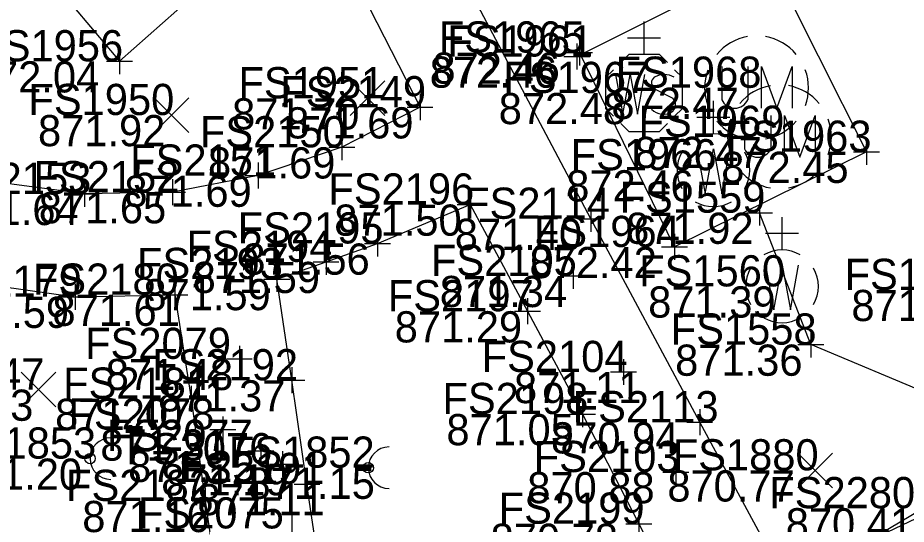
# Model space of a CAD drawing. Extents: x 1479420 to 1479833, y 379731 to 380103.
# Drawn here: x 1479654.58 to 1479688.81, y 379957.51 to 379977.01 of the extents above; entities that cross this region are included whole.
import ezdxf

# ---------------------------------------------------------------- set-up
doc = ezdxf.new("R2010")
doc.units = 0
for name, color, linetype in [('PV_X_Walk', 7, 'Continuous'), ('RD_X_Concrete_Pad', 7, 'Continuous'), ('SV_X_Random_Point', 7, 'Continuous'), ('SV_X_Shot_Marker', 7, 'Continuous'), ('SV_X_Text_Elevation', 7, 'Continuous'), ('SV_X_Text_Name', 7, 'Continuous'), ('UT_X_Gas', 7, 'Continuous'), ('UT_X_Misc_Cells', 7, 'Continuous'), ('UT_X_Unknown_Cells', 7, 'Continuous'), ('UT_X_Water', 7, 'Continuous'), ('UT_X_Water_Cells', 7, 'Continuous')]:
    doc.layers.add(name, color=color, linetype=linetype)

msp = doc.modelspace()

# ---------------------------------------------------------------- linework, layer by layer
at = {"layer": 'PV_X_Walk'}
for points in [[(1479508.898, 380098.739), (1479528.424, 380079.592), (1479545.906, 380063.234), (1479563.416, 380046.674), (1479583.683, 380027.557), (1479601.433, 380010.982), (1479618.885, 379994.721), (1479633.506, 379980.864), (1479639.156, 379975.367), (1479642.136, 379972.51), (1479646.219, 379969.763), (1479649.18, 379968.041), (1479652.865, 379966.819), (1479656.787, 379966.268), (1479660.633, 379966.347), (1479661.26, 379962.343), (1479661.797, 379958.407), (1479662.398, 379954.371), (1479663.052, 379950.601), (1479663.586, 379946.455), (1479663.663, 379946.474), (1479664.156, 379942.194)], [(1479666.468, 379980.646), (1479670.079, 379973.563), (1479667.067, 379972.021), (1479663.844, 379970.931), (1479660.54, 379970.294), (1479657.156, 379970.227), (1479653.854, 379970.663), (1479650.604, 379971.558), (1479648.889, 379972.524), (1479644.738, 379975.562), (1479637.768, 379982.016)], [(1479697.028, 379961.469), (1479684.159, 379955.33), (1479680.855, 379961.435), (1479676.661, 379969.27), (1479670.256, 379981.373)], [(1479667.32, 379947.167), (1479666.943, 379951.265), (1479666.294, 379955.174), (1479665.724, 379959.058), (1479665.135, 379963.052), (1479664.561, 379966.951), (1479666.457, 379967.611), (1479668.439, 379968.319), (1479672.009, 379969.818), (1479674.225, 379965.709), (1479676.339, 379961.752), (1479678.506, 379957.53), (1479680.531, 379953.578)]]:
    msp.add_lwpolyline(points, dxfattribs=at)
at = {"layer": 'RD_X_Concrete_Pad'}
for points in [[(1479657.099, 379986.097), (1479652.76, 379982.133), (1479658.499, 379975.334), (1479662.918, 379979.259), (1479657.078, 379986.008)], [(1479676.121, 379975.516), (1479683.555, 379979.257), (1479687.279, 379971.85), (1479679.881, 379968.184), (1479676.227, 379975.671)]]:
    msp.add_lwpolyline(points, dxfattribs=at)
at = {"layer": 'SV_X_Random_Point'}
for p, q in [((1479667.386, 379973.243), (1479668.72, 379974.578)), ((1479667.386, 379974.578), (1479668.72, 379973.243)), ((1479659.831, 379972.598), (1479661.165, 379973.933)), ((1479659.831, 379973.933), (1479661.165, 379972.598)), ((1479654.716, 379962.025), (1479656.05, 379963.36)), ((1479654.716, 379963.36), (1479656.05, 379962.025)), ((1479684.64, 379958.916), (1479685.974, 379960.251)), ((1479684.64, 379960.251), (1479685.974, 379958.916))]:
    msp.add_line(p, q, dxfattribs=at)
at = {"layer": 'SV_X_Shot_Marker'}
for p, q in [((1479676.121, 379976.016), (1479676.121, 379975.016)), ((1479676.227, 379976.171), (1479676.227, 379975.171)), ((1479658.499, 379975.834), (1479658.499, 379974.834)), ((1479675.727, 379975.671), (1479676.727, 379975.671)), ((1479676.227, 379975.671), (1479676.227, 379975.671)), ((1479657.999, 379975.334), (1479658.999, 379975.334)), ((1479658.499, 379975.334), (1479658.499, 379975.334)), ((1479675.621, 379975.516), (1479676.621, 379975.516)), ((1479676.121, 379975.516), (1479676.121, 379975.516)), ((1479670.079, 379974.063), (1479670.079, 379973.063)), ((1479669.579, 379973.563), (1479670.579, 379973.563)), ((1479670.079, 379973.563), (1479670.079, 379973.563)), ((1479667.067, 379972.521), (1479667.067, 379971.521)), ((1479687.279, 379972.35), (1479687.279, 379971.35)), ((1479666.567, 379972.021), (1479667.567, 379972.021)), ((1479667.067, 379972.021), (1479667.067, 379972.021)), ((1479686.779, 379971.85), (1479687.779, 379971.85)), ((1479687.279, 379971.85), (1479687.279, 379971.85)), ((1479663.844, 379971.431), (1479663.844, 379970.431)), ((1479660.54, 379970.794), (1479660.54, 379969.794)), ((1479663.344, 379970.931), (1479664.344, 379970.931)), ((1479663.844, 379970.931), (1479663.844, 379970.931)), ((1479657.156, 379970.727), (1479657.156, 379969.727)), ((1479656.656, 379970.227), (1479657.656, 379970.227)), ((1479657.156, 379970.227), (1479657.156, 379970.227)), ((1479660.04, 379970.294), (1479661.04, 379970.294)), ((1479660.54, 379970.294), (1479660.54, 379970.294)), ((1479672.009, 379970.318), (1479672.009, 379969.318)), ((1479671.509, 379969.818), (1479672.509, 379969.818)), ((1479672.009, 379969.818), (1479672.009, 379969.818)), ((1479676.661, 379969.77), (1479676.661, 379968.77)), ((1479683.162, 379970.005), (1479683.162, 379969.005)), ((1479682.662, 379969.505), (1479683.662, 379969.505)), ((1479683.162, 379969.505), (1479683.162, 379969.505)), ((1479676.161, 379969.27), (1479677.161, 379969.27)), ((1479676.661, 379969.27), (1479676.661, 379969.27)), ((1479668.439, 379968.819), (1479668.439, 379967.819)), ((1479679.881, 379968.684), (1479679.881, 379967.684)), ((1479666.457, 379968.111), (1479666.457, 379967.111)), ((1479667.939, 379968.319), (1479668.939, 379968.319)), ((1479668.439, 379968.319), (1479668.439, 379968.319)), ((1479679.381, 379968.184), (1479680.381, 379968.184)), ((1479679.881, 379968.184), (1479679.881, 379968.184)), ((1479664.561, 379967.451), (1479664.561, 379966.451)), ((1479665.957, 379967.611), (1479666.957, 379967.611)), ((1479666.457, 379967.611), (1479666.457, 379967.611)), ((1479675.979, 379967.57), (1479675.979, 379966.57)), ((1479675.479, 379967.07), (1479676.479, 379967.07)), ((1479675.979, 379967.07), (1479675.979, 379967.07)), ((1479656.787, 379966.768), (1479656.787, 379965.768)), ((1479660.633, 379966.847), (1479660.633, 379965.847)), ((1479664.061, 379966.951), (1479665.061, 379966.951)), ((1479664.561, 379966.951), (1479664.561, 379966.951)), ((1479660.133, 379966.347), (1479661.133, 379966.347)), ((1479660.633, 379966.347), (1479660.633, 379966.347)), ((1479656.287, 379966.268), (1479657.287, 379966.268)), ((1479656.787, 379966.268), (1479656.787, 379966.268)), ((1479674.225, 379966.209), (1479674.225, 379965.209)), ((1479673.725, 379965.709), (1479674.725, 379965.709)), ((1479674.225, 379965.709), (1479674.225, 379965.709)), ((1479685.134, 379964.926), (1479685.134, 379963.926)), ((1479663.118, 379964.375), (1479663.118, 379963.375)), ((1479684.634, 379964.426), (1479685.634, 379964.426)), ((1479685.134, 379964.426), (1479685.134, 379964.426)), ((1479662.618, 379963.875), (1479663.618, 379963.875)), ((1479663.118, 379963.875), (1479663.118, 379963.875)), ((1479677.924, 379963.871), (1479677.924, 379962.871)), ((1479665.135, 379963.552), (1479665.135, 379962.552)), ((1479677.424, 379963.371), (1479678.424, 379963.371)), ((1479677.924, 379963.371), (1479677.924, 379963.371)), ((1479664.635, 379963.052), (1479665.635, 379963.052)), ((1479665.135, 379963.052), (1479665.135, 379963.052)), ((1479661.26, 379962.843), (1479661.26, 379961.843)), ((1479660.76, 379962.343), (1479661.76, 379962.343)), ((1479661.26, 379962.343), (1479661.26, 379962.343)), ((1479676.339, 379962.252), (1479676.339, 379961.252)), ((1479680.855, 379961.935), (1479680.855, 379960.935)), ((1479662.476, 379961.658), (1479662.476, 379960.658)), ((1479675.839, 379961.752), (1479676.839, 379961.752)), ((1479676.339, 379961.752), (1479676.339, 379961.752)), ((1479680.355, 379961.435), (1479681.355, 379961.435)), ((1479680.855, 379961.435), (1479680.855, 379961.435)), ((1479661.976, 379961.158), (1479662.976, 379961.158)), ((1479662.476, 379961.158), (1479662.476, 379961.158)), ((1479663.944, 379960.834), (1479663.944, 379959.834)), ((1479663.444, 379960.334), (1479664.444, 379960.334)), ((1479663.944, 379960.334), (1479663.944, 379960.334)), ((1479664.775, 379960.32), (1479664.775, 379959.32)), ((1479679.938, 379960.018), (1479679.938, 379959.018)), ((1479664.275, 379959.82), (1479665.275, 379959.82)), ((1479664.775, 379959.82), (1479664.775, 379959.82)), ((1479665.724, 379959.558), (1479665.724, 379958.558)), ((1479679.438, 379959.518), (1479680.438, 379959.518)), ((1479679.938, 379959.518), (1479679.938, 379959.518)), ((1479661.797, 379958.907), (1479661.797, 379957.907)), ((1479665.224, 379959.058), (1479666.224, 379959.058)), ((1479665.724, 379959.058), (1479665.724, 379959.058)), ((1479661.297, 379958.407), (1479662.297, 379958.407)), ((1479661.797, 379958.407), (1479661.797, 379958.407)), ((1479665.144, 379957.847), (1479665.144, 379956.847)), ((1479678.506, 379958.03), (1479678.506, 379957.03)), ((1479678.006, 379957.53), (1479679.006, 379957.53)), ((1479678.506, 379957.53), (1479678.506, 379957.53))]:
    msp.add_line(p, q, dxfattribs=at)
at = {"layer": 'UT_X_Gas'}
msp.add_lwpolyline([(1479590.076, 380006.869), (1479598.835, 379999.983), (1479606.591, 379993.985), (1479615.604, 379985.249), (1479623.747, 379977.629), (1479632.184, 379969.538), (1479638.836, 379962.809), (1479646.785, 379955.438), (1479652.981, 379949.433), (1479657.465, 379945.964), (1479660.591, 379945.024), (1479670.935, 379949.08), (1479679.157, 379953.065), (1479685.442, 379955.742), (1479689.462, 379958.127), (1479696.956, 379963.013), (1479705.088, 379967.488), (1479713.465, 379971.226), (1479723.024, 379975.676), (1479732.065, 379980.116), (1479742.535, 379985.018)], dxfattribs=at)
at = {"layer": 'UT_X_Misc_Cells'}
for centre in [(1479657.365, 379960.036), (1479668.087, 379959.686)]:
    msp.add_circle(centre, 0.2, dxfattribs=at)
for centre in [(1479658.165, 379960.036), (1479668.887, 379959.686)]:
    msp.add_arc(centre, 0.8, 90, 270, dxfattribs=at)
at = {"layer": 'UT_X_Unknown_Cells'}
for p, q in [((1479681.705, 379975.129), (1479681.705, 379973.849)), ((1479682.714, 379975.129), (1479682.714, 379973.849)), ((1479683.047, 379974.314), (1479683.047, 379974.314)), ((1479682.588, 379973.24), (1479682.588, 379971.96)), ((1479683.597, 379973.24), (1479683.597, 379971.96)), ((1479683.93, 379972.425), (1479683.93, 379972.425))]:
    msp.add_line(p, q, dxfattribs=at)
for points in [[(1479683.235, 379973.529), (1479683.235, 379975.129), (1479683.829, 379973.529), (1479684.42, 379975.129), (1479684.42, 379973.529)], [(1479684.118, 379971.64), (1479684.118, 379973.24), (1479684.712, 379971.64), (1479685.303, 379973.24), (1479685.303, 379971.64)]]:
    msp.add_lwpolyline(points, dxfattribs=at)
for centre, radius, start, end in [((1479683.047, 379974.314), 2, 100.0806, 140.0721), ((1479683.047, 379974.314), 2, 40.0577, 80.1061), ((1479683.047, 379974.314), 2, 160.0169, 200.0392), ((1479683.047, 379974.314), 2, 340.0169, 20.0392), ((1479683.93, 379972.425), 2, 100.0806, 140.0721), ((1479683.93, 379972.425), 2, 40.0577, 80.1061), ((1479682.209, 379974.086), 0.557, 205.1924, 334.8076), ((1479683.047, 379974.314), 2, 220.0577, 260.0473), ((1479683.93, 379972.425), 2, 160.0169, 200.0392), ((1479683.047, 379974.314), 2, 280.0114, 320.0264), ((1479683.93, 379972.425), 2, 340.0169, 20.0392), ((1479683.092, 379972.197), 0.557, 205.1924, 334.8076), ((1479683.93, 379972.425), 2, 220.0577, 260.0473), ((1479683.93, 379972.425), 2, 280.0114, 320.0264)]:
    msp.add_arc(centre, radius, start, end, dxfattribs=at)
at = {"layer": 'UT_X_Water'}
msp.add_lwpolyline([(1479708.028, 379936.357), (1479707.494, 379936.973), (1479705.885, 379940.546), (1479703.244, 379946.083), (1479697.845, 379955.578), (1479694.57, 379960.481), (1479685.134, 379964.426), (1479683.162, 379969.505)], dxfattribs=at)
at = {"layer": 'UT_X_Water_Cells'}
for p, q in [((1479678.714, 379975.594), (1479678.714, 379976.864)), ((1479679.349, 379976.229), (1479678.076, 379976.229)), ((1479679.117, 379974.278), (1479679.819, 379973.911)), ((1479678.714, 379974.113), (1479678.714, 379974.113)), ((1479681.383, 379972.538), (1479681.383, 379973.81)), ((1479682.018, 379973.175), (1479680.746, 379973.175)), ((1479681.383, 379971.138), (1479681.383, 379971.138)), ((1479684.03, 379968.066), (1479684.03, 379969.338)), ((1479684.665, 379968.703), (1479683.393, 379968.703)), ((1479684.03, 379966.666), (1479684.03, 379966.666))]:
    msp.add_line(p, q, dxfattribs=at)
for points in [[(1479679.611, 379975.289), (1479679.306, 379975.594), (1479678.121, 379975.594), (1479677.817, 379975.293)], [(1479677.537, 379975.009), (1479677.232, 379974.706), (1479677.232, 379973.521), (1479677.534, 379973.219)], [(1479679.891, 379973.219), (1479680.194, 379973.521), (1479680.194, 379974.706), (1479679.891, 379975.009)], [(1479677.606, 379974.823), (1479677.889, 379973.296), (1479678.171, 379974.823), (1479678.454, 379973.296), (1479678.741, 379974.823)], [(1479677.814, 379972.939), (1479678.121, 379972.633), (1479679.306, 379972.633), (1479679.611, 379972.936)], [(1479680.746, 379971.958), (1479681.065, 379970.235), (1479681.383, 379971.958), (1479681.703, 379970.235), (1479682.02, 379971.958)], [(1479683.393, 379967.486), (1479683.712, 379965.763), (1479684.03, 379967.486), (1479684.35, 379965.763), (1479684.667, 379967.486)]]:
    msp.add_lwpolyline(points, dxfattribs=at)
for centre, radius, start, end in [((1479679.267, 379974.503), 0.271, 126.2587, 236.3676), ((1479679.491, 379974.019), 0.8, 61.3463, 118.6537), ((1479679.591, 379973.663), 0.339, 311.4883, 47.9358), ((1479679.458, 379973.931), 0.633, 223.6695, 304.3963), ((1479681.383, 379971.14), 1.4, 60.0184, 120.0157), ((1479681.383, 379971.14), 1.4, 150.0184, 209.9816), ((1479681.383, 379971.14), 1.4, 330.0184, 29.9816), ((1479681.383, 379971.14), 1.4, 239.9843, 299.9816), ((1479684.03, 379966.668), 1.4, 60.0184, 120.0157), ((1479684.03, 379966.668), 1.4, 150.0184, 209.9816), ((1479684.03, 379966.668), 1.4, 330.0184, 29.9816), ((1479684.03, 379966.668), 1.4, 239.9843, 299.9816)]:
    msp.add_arc(centre, radius, start, end, dxfattribs=at)

# ---------------------------------------------------------------- texts
at = {"layer": 'SV_X_Text_Elevation'}
for s, p in [('872.46', (1479670.558, 379974.471)), ('872.04', (1479652.811, 379974.134)), ('872.46', (1479670.452, 379974.316)), ('872.47', (1479677.454, 379973.114)), ('871.70', (1479662.838, 379972.71)), ('872.48', (1479673.111, 379972.913)), ('871.69', (1479664.921, 379972.363)), ('871.92', (1479655.359, 379972.065)), ('872.47', (1479678.337, 379971.225)), ('871.69', (1479661.909, 379970.821)), ('872.45', (1479681.686, 379970.65)), ('872.46', (1479675.714, 379969.938)), ('871.69', (1479658.686, 379969.731)), ('871.64', (1479652.017, 379969.027)), ('871.65', (1479655.391, 379969.094)), ('871.50', (1479666.775, 379968.618)), ('871.92', (1479678.023, 379968.305)), ('871.40', (1479671.418, 379968.07)), ('871.56', (1479663.234, 379967.119)), ('872.42', (1479674.297, 379966.984)), ('871.59', (1479661.318, 379966.411)), ('871.34', (1479670.84, 379965.87)), ('871.59', (1479659.422, 379965.751)), ('871.39', (1479678.872, 379965.466)), ('871.61', (1479655.918, 379965.147)), ('871.23', (1479686.702, 379965.331)), ('871.59', (1479651.648, 379965.068)), ('871.29', (1479669.105, 379964.509)), ('871.36', (1479679.91, 379963.226)), ('871.48', (1479657.969, 379962.675)), ('871.11', (1479673.701, 379962.171)), ('871.37', (1479659.986, 379961.852)), ('871.23', (1479650.272, 379961.493)), ('871.40', (1479656.017, 379961.143)), ('871.05', (1479671.096, 379960.552)), ('870.94', (1479675.129, 379960.235)), ('871.31', (1479657.761, 379959.958)), ('871.25', (1479658.833, 379959.134)), ('871.20', (1479652.15, 379958.836)), ('871.19', (1479660.109, 379958.62)), ('871.15', (1479663.43, 379958.486)), ('870.88', (1479674.212, 379958.318)), ('870.77', (1479679.61, 379958.383)), ('871.11', (1479661.501, 379957.858)), ('871.16', (1479657.065, 379957.207)), ('870.41', (1479684.17, 379956.927)), ('870.78', (1479672.799, 379956.33))]:
    msp.add_text(s, height=1.2, dxfattribs=at).set_placement(p)
at = {"layer": 'SV_X_Text_Name'}
for s, p in [('FS1965', (1479670.804, 379975.671)), ('FS1961', (1479671.132, 379975.516)), ('FS1956', (1479653.02, 379975.334)), ('FS1967', (1479673.291, 379974.113)), ('FS1968', (1479677.615, 379974.314)), ('FS1951', (1479663.083, 379973.91)), ('FS2149', (1479664.694, 379973.563)), ('FS1950', (1479654.99, 379973.265)), ('FS1969', (1479678.498, 379972.425)), ('FS2150', (1479661.597, 379972.021)), ('FS1963', (1479681.856, 379971.85)), ('FS1966', (1479675.885, 379971.138)), ('FS2151', (1479658.912, 379970.931)), ('FS2152', (1479655.184, 379970.294)), ('FS2153', (1479651.79, 379970.227)), ('FS2196', (1479666.549, 379969.818)), ('FS2114', (1479671.778, 379969.27)), ('FS1559', (1479677.768, 379969.505)), ('FS2195', (1479663.054, 379968.319)), ('FS1964', (1479674.468, 379968.184)), ('FS2194', (1479661.082, 379967.611)), ('FS2193', (1479659.176, 379966.951)), ('FS2105', (1479670.5, 379967.07)), ('FS1560', (1479678.522, 379966.666)), ('FS1879', (1479686.438, 379966.531)), ('FS2179', (1479651.431, 379966.268)), ('FS2180', (1479655.163, 379966.347)), ('FS2197', (1479668.84, 379965.709)), ('FS1558', (1479679.74, 379964.426)), ('FS2079', (1479657.175, 379963.875)), ('FS2104', (1479672.454, 379963.371)), ('FS2192', (1479659.76, 379963.052)), ('FS1847', (1479649.989, 379962.693)), ('FS2181', (1479656.328, 379962.343)), ('FS2198', (1479670.945, 379961.752)), ('FS2113', (1479675.962, 379961.435)), ('FS2078', (1479656.533, 379961.158)), ('FS2077', (1479658.011, 379960.334)), ('FS1853', (1479651.98, 379960.036)), ('FS2076', (1479658.766, 379959.82)), ('FS1852', (1479662.712, 379959.686)), ('FS2103', (1479674.459, 379959.518)), ('FS1880', (1479679.818, 379959.583)), ('FS2191', (1479660.773, 379959.058)), ('FS2182', (1479656.441, 379958.407)), ('FS2280', (1479683.538, 379958.127)), ('FS2075', (1479659.211, 379957.347)), ('FS2199', (1479673.112, 379957.53))]:
    msp.add_text(s, height=1.2, dxfattribs=at).set_placement(p)

doc.saveas('drawing.dxf')
